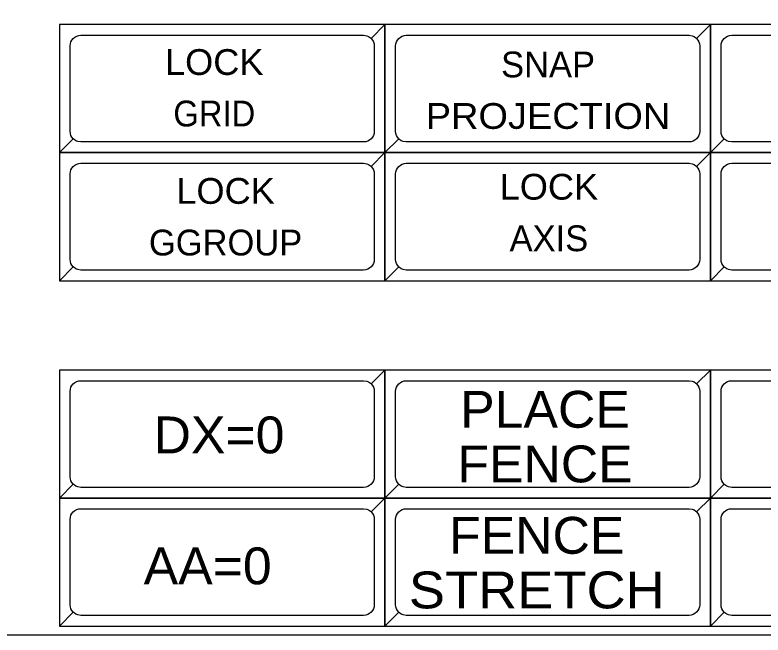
# Model space of a CAD drawing. Extents: x 16898 to 16911.6, y 15837.8 to 15842.
# Drawn here: x 16905.198 to 16906.776, y 15839.972 to 15841.28 of the extents above; entities that cross this region are included whole.
import ezdxf
from ezdxf.enums import TextEntityAlignment as Align

# ---------------------------------------------------------------- set-up
doc = ezdxf.new("R2010")
doc.units = 0
doc.header["$LTSCALE"] = 0.018
for name, color, linetype, lineweight in [('1', 7, 'Continuous', 25), ('2', 7, 'Continuous', 13), ('5', 7, 'Continuous', 13)]:
    doc.layers.add(name, color=color, linetype=linetype, lineweight=lineweight)

msp = doc.modelspace()

# ---------------------------------------------------------------- linework, layer by layer
at = {"layer": '1'}
for points in [[(16897.9955, 15839.9723), (16897.9955, 15842.0124), (16911.4764, 15842.0124), (16911.5674, 15841.9251), (16911.5674, 15840.0599), (16911.4764, 15839.9723)], [(16905.292, 15840.9896), (16905.9784, 15840.9896), (16905.9784, 15841.2596), (16905.292, 15841.2596)], [(16905.292, 15840.9896), (16905.9784, 15840.9896), (16905.9784, 15841.2596), (16905.9493, 15841.2305), (16905.9521, 15841.2271), (16905.9542, 15841.2232), (16905.9554, 15841.219), (16905.9559, 15841.2146), (16905.9559, 15841.0346), (16905.9554, 15841.0302), (16905.9542, 15841.026), (16905.9521, 15841.0221), (16905.9493, 15841.0187), (16905.9493, 15841.0187), (16905.9459, 15841.0159), (16905.942, 15841.0138), (16905.9378, 15841.0125), (16905.9334, 15841.0121), (16905.337, 15841.0121), (16905.3304, 15841.0131), (16905.3264, 15841.0148), (16905.3227, 15841.0172), (16905.3211, 15841.0187)], [(16905.9784, 15841.2596), (16905.292, 15841.2596), (16905.292, 15840.9896), (16905.3211, 15841.0187), (16905.3183, 15841.0221), (16905.3162, 15841.026), (16905.3149, 15841.0302), (16905.3145, 15841.0346), (16905.3145, 15841.2146), (16905.3149, 15841.219), (16905.3162, 15841.2232), (16905.3183, 15841.2271), (16905.3211, 15841.2305), (16905.3211, 15841.2305), (16905.3245, 15841.2333), (16905.3284, 15841.2354), (16905.3326, 15841.2366), (16905.337, 15841.2371), (16905.9334, 15841.2371), (16905.94, 15841.2361), (16905.944, 15841.2344), (16905.9477, 15841.232), (16905.9493, 15841.2305)], [(16905.9784, 15840.9896), (16906.6648, 15840.9896), (16906.6648, 15841.2596), (16905.9784, 15841.2596)], [(16905.9784, 15840.9896), (16906.6648, 15840.9896), (16906.6648, 15841.2596), (16906.6357, 15841.2305), (16906.6385, 15841.2271), (16906.6406, 15841.2232), (16906.6418, 15841.219), (16906.6423, 15841.2146), (16906.6423, 15841.0346), (16906.6418, 15841.0302), (16906.6406, 15841.026), (16906.6385, 15841.0221), (16906.6357, 15841.0187), (16906.6357, 15841.0187), (16906.6323, 15841.0159), (16906.6284, 15841.0138), (16906.6242, 15841.0125), (16906.6198, 15841.0121), (16906.0234, 15841.0121), (16906.0168, 15841.0131), (16906.0128, 15841.0148), (16906.0091, 15841.0172), (16906.0075, 15841.0187)], [(16906.6648, 15841.2596), (16905.9784, 15841.2596), (16905.9784, 15840.9896), (16906.0075, 15841.0187), (16906.0047, 15841.0221), (16906.0026, 15841.026), (16906.0013, 15841.0302), (16906.0009, 15841.0346), (16906.0009, 15841.2146), (16906.0013, 15841.219), (16906.0026, 15841.2232), (16906.0047, 15841.2271), (16906.0075, 15841.2305), (16906.0075, 15841.2305), (16906.0109, 15841.2333), (16906.0148, 15841.2354), (16906.019, 15841.2366), (16906.0234, 15841.2371), (16906.6198, 15841.2371), (16906.6264, 15841.2361), (16906.6304, 15841.2344), (16906.6341, 15841.232), (16906.6357, 15841.2305)], [(16906.6648, 15840.9896), (16907.3512, 15840.9896), (16907.3512, 15841.2596), (16906.6648, 15841.2596)], [(16906.6648, 15840.9896), (16907.3512, 15840.9896), (16907.3512, 15841.2596), (16907.3221, 15841.2305), (16907.3249, 15841.2271), (16907.327, 15841.2232), (16907.3282, 15841.219), (16907.3287, 15841.2146), (16907.3287, 15841.0346), (16907.3282, 15841.0302), (16907.327, 15841.026), (16907.3249, 15841.0221), (16907.3221, 15841.0187), (16907.3221, 15841.0187), (16907.3187, 15841.0159), (16907.3148, 15841.0138), (16907.3106, 15841.0125), (16907.3062, 15841.0121), (16906.7098, 15841.0121), (16906.7032, 15841.0131), (16906.6992, 15841.0148), (16906.6955, 15841.0172), (16906.6939, 15841.0187)], [(16907.3512, 15841.2596), (16906.6648, 15841.2596), (16906.6648, 15840.9896), (16906.6939, 15841.0187), (16906.6911, 15841.0221), (16906.689, 15841.026), (16906.6877, 15841.0302), (16906.6873, 15841.0346), (16906.6873, 15841.2146), (16906.6877, 15841.219), (16906.689, 15841.2232), (16906.6911, 15841.2271), (16906.6939, 15841.2305), (16906.6939, 15841.2305), (16906.6973, 15841.2333), (16906.7012, 15841.2354), (16906.7054, 15841.2366), (16906.7098, 15841.2371), (16907.3062, 15841.2371), (16907.3128, 15841.2361), (16907.3168, 15841.2344), (16907.3205, 15841.232), (16907.3221, 15841.2305)], [(16905.292, 15840.7196), (16905.9784, 15840.7196), (16905.9784, 15840.9896), (16905.292, 15840.9896)], [(16905.292, 15840.7196), (16905.9784, 15840.7196), (16905.9784, 15840.9896), (16905.9493, 15840.9605), (16905.9521, 15840.9571), (16905.9542, 15840.9532), (16905.9554, 15840.949), (16905.9559, 15840.9446), (16905.9559, 15840.7646), (16905.9554, 15840.7602), (16905.9542, 15840.756), (16905.9521, 15840.7521), (16905.9493, 15840.7487), (16905.9493, 15840.7487), (16905.9459, 15840.7459), (16905.942, 15840.7438), (16905.9378, 15840.7425), (16905.9334, 15840.7421), (16905.337, 15840.7421), (16905.3304, 15840.7431), (16905.3264, 15840.7448), (16905.3227, 15840.7472), (16905.3211, 15840.7487)], [(16905.9784, 15840.9896), (16905.292, 15840.9896), (16905.292, 15840.7196), (16905.3211, 15840.7487), (16905.3183, 15840.7521), (16905.3162, 15840.756), (16905.3149, 15840.7602), (16905.3145, 15840.7646), (16905.3145, 15840.9446), (16905.3149, 15840.949), (16905.3162, 15840.9532), (16905.3183, 15840.9571), (16905.3211, 15840.9605), (16905.3211, 15840.9605), (16905.3245, 15840.9633), (16905.3284, 15840.9654), (16905.3326, 15840.9666), (16905.337, 15840.9671), (16905.9334, 15840.9671), (16905.94, 15840.9661), (16905.944, 15840.9644), (16905.9477, 15840.962), (16905.9493, 15840.9605)], [(16905.9784, 15840.7196), (16906.6648, 15840.7196), (16906.6648, 15840.9896), (16905.9784, 15840.9896)], [(16905.9784, 15840.7196), (16906.6648, 15840.7196), (16906.6648, 15840.9896), (16906.6357, 15840.9605), (16906.6385, 15840.9571), (16906.6406, 15840.9532), (16906.6418, 15840.949), (16906.6423, 15840.9446), (16906.6423, 15840.7646), (16906.6418, 15840.7602), (16906.6406, 15840.756), (16906.6385, 15840.7521), (16906.6357, 15840.7487), (16906.6357, 15840.7487), (16906.6323, 15840.7459), (16906.6284, 15840.7438), (16906.6242, 15840.7425), (16906.6198, 15840.7421), (16906.0234, 15840.7421), (16906.0168, 15840.7431), (16906.0128, 15840.7448), (16906.0091, 15840.7472), (16906.0075, 15840.7487)], [(16906.6648, 15840.9896), (16905.9784, 15840.9896), (16905.9784, 15840.7196), (16906.0075, 15840.7487), (16906.0047, 15840.7521), (16906.0026, 15840.756), (16906.0013, 15840.7602), (16906.0009, 15840.7646), (16906.0009, 15840.9446), (16906.0013, 15840.949), (16906.0026, 15840.9532), (16906.0047, 15840.9571), (16906.0075, 15840.9605), (16906.0075, 15840.9605), (16906.0109, 15840.9633), (16906.0148, 15840.9654), (16906.019, 15840.9666), (16906.0234, 15840.9671), (16906.6198, 15840.9671), (16906.6264, 15840.9661), (16906.6304, 15840.9644), (16906.6341, 15840.962), (16906.6357, 15840.9605)], [(16906.6648, 15840.7196), (16907.3512, 15840.7196), (16907.3512, 15840.9896), (16906.6648, 15840.9896)], [(16906.6648, 15840.7196), (16907.3512, 15840.7196), (16907.3512, 15840.9896), (16907.3221, 15840.9605), (16907.3249, 15840.9571), (16907.327, 15840.9532), (16907.3282, 15840.949), (16907.3287, 15840.9446), (16907.3287, 15840.7646), (16907.3282, 15840.7602), (16907.327, 15840.756), (16907.3249, 15840.7521), (16907.3221, 15840.7487), (16907.3221, 15840.7487), (16907.3187, 15840.7459), (16907.3148, 15840.7438), (16907.3106, 15840.7425), (16907.3062, 15840.7421), (16906.7098, 15840.7421), (16906.7032, 15840.7431), (16906.6992, 15840.7448), (16906.6955, 15840.7472), (16906.6939, 15840.7487)], [(16907.3512, 15840.9896), (16906.6648, 15840.9896), (16906.6648, 15840.7196), (16906.6939, 15840.7487), (16906.6911, 15840.7521), (16906.689, 15840.756), (16906.6877, 15840.7602), (16906.6873, 15840.7646), (16906.6873, 15840.9446), (16906.6877, 15840.949), (16906.689, 15840.9532), (16906.6911, 15840.9571), (16906.6939, 15840.9605), (16906.6939, 15840.9605), (16906.6973, 15840.9633), (16906.7012, 15840.9654), (16906.7054, 15840.9666), (16906.7098, 15840.9671), (16907.3062, 15840.9671), (16907.3128, 15840.9661), (16907.3168, 15840.9644), (16907.3205, 15840.962), (16907.3221, 15840.9605)], [(16905.292, 15840.2612), (16905.9784, 15840.2612), (16905.9784, 15840.5312), (16905.292, 15840.5312)], [(16905.292, 15840.2612), (16905.9784, 15840.2612), (16905.9784, 15840.5312), (16905.9493, 15840.5021), (16905.9521, 15840.4987), (16905.9542, 15840.4948), (16905.9554, 15840.4906), (16905.9559, 15840.4862), (16905.9559, 15840.3062), (16905.9554, 15840.3018), (16905.9542, 15840.2976), (16905.9521, 15840.2937), (16905.9493, 15840.2903), (16905.9493, 15840.2903), (16905.9459, 15840.2875), (16905.942, 15840.2854), (16905.9378, 15840.2841), (16905.9334, 15840.2837), (16905.337, 15840.2837), (16905.3304, 15840.2847), (16905.3264, 15840.2864), (16905.3227, 15840.2888), (16905.3211, 15840.2903)], [(16905.9784, 15840.5312), (16905.292, 15840.5312), (16905.292, 15840.2612), (16905.3211, 15840.2903), (16905.3183, 15840.2937), (16905.3162, 15840.2976), (16905.3149, 15840.3018), (16905.3145, 15840.3062), (16905.3145, 15840.4862), (16905.3149, 15840.4906), (16905.3162, 15840.4948), (16905.3183, 15840.4987), (16905.3211, 15840.5021), (16905.3211, 15840.5021), (16905.3245, 15840.5049), (16905.3284, 15840.507), (16905.3326, 15840.5082), (16905.337, 15840.5087), (16905.9334, 15840.5087), (16905.94, 15840.5077), (16905.944, 15840.506), (16905.9477, 15840.5036), (16905.9493, 15840.5021)], [(16905.9784, 15840.2612), (16906.6648, 15840.2612), (16906.6648, 15840.5312), (16905.9784, 15840.5312)], [(16905.9784, 15840.2612), (16906.6648, 15840.2612), (16906.6648, 15840.5312), (16906.6357, 15840.5021), (16906.6385, 15840.4987), (16906.6406, 15840.4948), (16906.6418, 15840.4906), (16906.6423, 15840.4862), (16906.6423, 15840.3062), (16906.6418, 15840.3018), (16906.6406, 15840.2976), (16906.6385, 15840.2937), (16906.6357, 15840.2903), (16906.6357, 15840.2903), (16906.6323, 15840.2875), (16906.6284, 15840.2854), (16906.6242, 15840.2841), (16906.6198, 15840.2837), (16906.0234, 15840.2837), (16906.0168, 15840.2847), (16906.0128, 15840.2864), (16906.0091, 15840.2888), (16906.0075, 15840.2903)], [(16906.6648, 15840.5312), (16905.9784, 15840.5312), (16905.9784, 15840.2612), (16906.0075, 15840.2903), (16906.0047, 15840.2937), (16906.0026, 15840.2976), (16906.0013, 15840.3018), (16906.0009, 15840.3062), (16906.0009, 15840.4862), (16906.0013, 15840.4906), (16906.0026, 15840.4948), (16906.0047, 15840.4987), (16906.0075, 15840.5021), (16906.0075, 15840.5021), (16906.0109, 15840.5049), (16906.0148, 15840.507), (16906.019, 15840.5082), (16906.0234, 15840.5087), (16906.6198, 15840.5087), (16906.6264, 15840.5077), (16906.6304, 15840.506), (16906.6341, 15840.5036), (16906.6357, 15840.5021)], [(16906.6648, 15840.2612), (16907.3512, 15840.2612), (16907.3512, 15840.5312), (16906.6648, 15840.5312)], [(16906.6648, 15840.2612), (16907.3512, 15840.2612), (16907.3512, 15840.5312), (16907.3221, 15840.5021), (16907.3249, 15840.4987), (16907.327, 15840.4948), (16907.3282, 15840.4906), (16907.3287, 15840.4862), (16907.3287, 15840.3062), (16907.3282, 15840.3018), (16907.327, 15840.2976), (16907.3249, 15840.2937), (16907.3221, 15840.2903), (16907.3221, 15840.2903), (16907.3187, 15840.2875), (16907.3148, 15840.2854), (16907.3106, 15840.2841), (16907.3062, 15840.2837), (16906.7098, 15840.2837), (16906.7032, 15840.2847), (16906.6992, 15840.2864), (16906.6955, 15840.2888), (16906.6939, 15840.2903)], [(16907.3512, 15840.5312), (16906.6648, 15840.5312), (16906.6648, 15840.2612), (16906.6939, 15840.2903), (16906.6911, 15840.2937), (16906.689, 15840.2976), (16906.6877, 15840.3018), (16906.6873, 15840.3062), (16906.6873, 15840.4862), (16906.6877, 15840.4906), (16906.689, 15840.4948), (16906.6911, 15840.4987), (16906.6939, 15840.5021), (16906.6939, 15840.5021), (16906.6973, 15840.5049), (16906.7012, 15840.507), (16906.7054, 15840.5082), (16906.7098, 15840.5087), (16907.3062, 15840.5087), (16907.3128, 15840.5077), (16907.3168, 15840.506), (16907.3205, 15840.5036), (16907.3221, 15840.5021)], [(16905.292, 15839.9912), (16905.9784, 15839.9912), (16905.9784, 15840.2612), (16905.292, 15840.2612)], [(16905.292, 15839.9912), (16905.9784, 15839.9912), (16905.9784, 15840.2612), (16905.9493, 15840.2321), (16905.9521, 15840.2287), (16905.9542, 15840.2248), (16905.9554, 15840.2206), (16905.9559, 15840.2162), (16905.9559, 15840.0362), (16905.9554, 15840.0318), (16905.9542, 15840.0276), (16905.9521, 15840.0237), (16905.9493, 15840.0203), (16905.9493, 15840.0203), (16905.9459, 15840.0175), (16905.942, 15840.0154), (16905.9378, 15840.0141), (16905.9334, 15840.0137), (16905.337, 15840.0137), (16905.3304, 15840.0147), (16905.3264, 15840.0164), (16905.3227, 15840.0188), (16905.3211, 15840.0203)], [(16905.9784, 15840.2612), (16905.292, 15840.2612), (16905.292, 15839.9912), (16905.3211, 15840.0203), (16905.3183, 15840.0237), (16905.3162, 15840.0276), (16905.3149, 15840.0318), (16905.3145, 15840.0362), (16905.3145, 15840.2162), (16905.3149, 15840.2206), (16905.3162, 15840.2248), (16905.3183, 15840.2287), (16905.3211, 15840.2321), (16905.3211, 15840.2321), (16905.3245, 15840.2349), (16905.3284, 15840.237), (16905.3326, 15840.2382), (16905.337, 15840.2387), (16905.9334, 15840.2387), (16905.94, 15840.2377), (16905.944, 15840.236), (16905.9477, 15840.2336), (16905.9493, 15840.2321)], [(16905.9784, 15839.9912), (16906.6648, 15839.9912), (16906.6648, 15840.2612), (16905.9784, 15840.2612)], [(16905.9784, 15839.9912), (16906.6648, 15839.9912), (16906.6648, 15840.2612), (16906.6357, 15840.2321), (16906.6385, 15840.2287), (16906.6406, 15840.2248), (16906.6418, 15840.2206), (16906.6423, 15840.2162), (16906.6423, 15840.0362), (16906.6418, 15840.0318), (16906.6406, 15840.0276), (16906.6385, 15840.0237), (16906.6357, 15840.0203), (16906.6357, 15840.0203), (16906.6323, 15840.0175), (16906.6284, 15840.0154), (16906.6242, 15840.0141), (16906.6198, 15840.0137), (16906.0234, 15840.0137), (16906.0168, 15840.0147), (16906.0128, 15840.0164), (16906.0091, 15840.0188), (16906.0075, 15840.0203)], [(16906.6648, 15840.2612), (16905.9784, 15840.2612), (16905.9784, 15839.9912), (16906.0075, 15840.0203), (16906.0047, 15840.0237), (16906.0026, 15840.0276), (16906.0013, 15840.0318), (16906.0009, 15840.0362), (16906.0009, 15840.2162), (16906.0013, 15840.2206), (16906.0026, 15840.2248), (16906.0047, 15840.2287), (16906.0075, 15840.2321), (16906.0075, 15840.2321), (16906.0109, 15840.2349), (16906.0148, 15840.237), (16906.019, 15840.2382), (16906.0234, 15840.2387), (16906.6198, 15840.2387), (16906.6264, 15840.2377), (16906.6304, 15840.236), (16906.6341, 15840.2336), (16906.6357, 15840.2321)], [(16906.6648, 15839.9912), (16907.3512, 15839.9912), (16907.3512, 15840.2612), (16906.6648, 15840.2612)], [(16906.6648, 15839.9912), (16907.3512, 15839.9912), (16907.3512, 15840.2612), (16907.3221, 15840.2321), (16907.3249, 15840.2287), (16907.327, 15840.2248), (16907.3282, 15840.2206), (16907.3287, 15840.2162), (16907.3287, 15840.0362), (16907.3282, 15840.0318), (16907.327, 15840.0276), (16907.3249, 15840.0237), (16907.3221, 15840.0203), (16907.3221, 15840.0203), (16907.3187, 15840.0175), (16907.3148, 15840.0154), (16907.3106, 15840.0141), (16907.3062, 15840.0137), (16906.7098, 15840.0137), (16906.7032, 15840.0147), (16906.6992, 15840.0164), (16906.6955, 15840.0188), (16906.6939, 15840.0203)], [(16907.3512, 15840.2612), (16906.6648, 15840.2612), (16906.6648, 15839.9912), (16906.6939, 15840.0203), (16906.6911, 15840.0237), (16906.689, 15840.0276), (16906.6877, 15840.0318), (16906.6873, 15840.0362), (16906.6873, 15840.2162), (16906.6877, 15840.2206), (16906.689, 15840.2248), (16906.6911, 15840.2287), (16906.6939, 15840.2321), (16906.6939, 15840.2321), (16906.6973, 15840.2349), (16906.7012, 15840.237), (16906.7054, 15840.2382), (16906.7098, 15840.2387), (16907.3062, 15840.2387), (16907.3128, 15840.2377), (16907.3168, 15840.236), (16907.3205, 15840.2336), (16907.3221, 15840.2321)]]:
    msp.add_lwpolyline(points, close=True, dxfattribs=at)
at = {"layer": '2'}
msp.add_lwpolyline([(16897.9955, 15839.9723), (16897.9955, 15842.0124), (16911.4764, 15842.0124), (16911.5674, 15841.9251), (16911.5674, 15840.0599), (16911.4764, 15839.9723)], close=True, dxfattribs=at)

# ---------------------------------------------------------------- texts
at = {"layer": '5'}
for s, height, width, p in [('LOCK', 0.0544, 1.05, (16905.6184, 15841.1535)), ('GRID', 0.0544, 0.95, (16905.6185, 15841.0449)), ('PROJECTION', 0.0544, 1.1, (16906.3223, 15841.0398)), ('LOCK', 0.0544, 1.05, (16906.3242, 15840.8905)), ('LOCK', 0.0544, 1.05, (16905.6423, 15840.8817)), ('PLACE', 0.07772, 1.05, (16906.316, 15840.4095)), ('DX=0', 0.07772, 1.05, (16905.6285, 15840.3555)), ('FENCE', 0.07772, 1.05, (16906.316, 15840.2943)), ('FENCE', 0.07772, 1.05, (16906.2985, 15840.1437)), ('AA=0', 0.07772, 1.05, (16905.6045, 15840.0793)), ('STRETCH', 0.07772, 1.1, (16906.2987, 15840.0285))]:
    msp.add_text(s, height=height, dxfattribs=dict(at, width=width)).set_placement(p, align=Align.CENTER)
for s, p in [('SNAP', (16906.3224, 15841.1484)), ('AXIS', (16906.3242, 15840.7818)), ('GGROUP', (16905.6423, 15840.7728))]:
    msp.add_text(s, height=0.0544, dxfattribs=at).set_placement(p, align=Align.CENTER)

doc.saveas('drawing.dxf')
